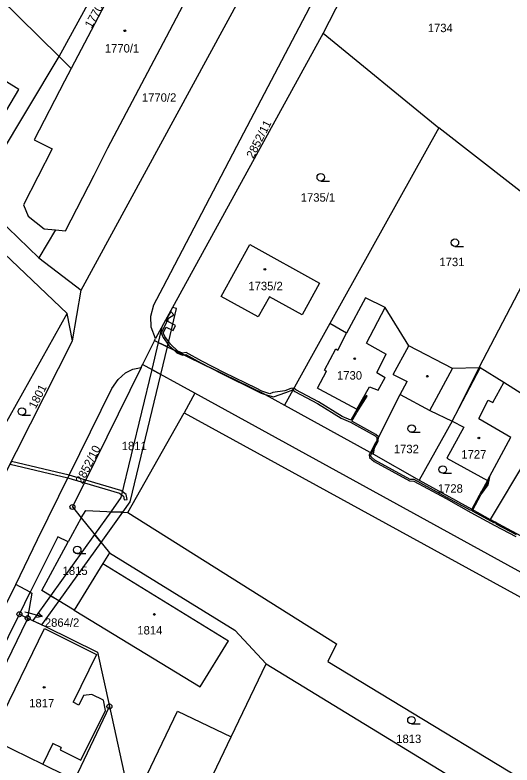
# Model space of a CAD drawing. Extents: x -562167 to -556918, y -1077891 to -1070763.
# Drawn here: x -560310.5 to -560210.1, y -1076020.6 to -1075869.3 of the extents above; entities that cross this region are included whole.
import ezdxf

# ---------------------------------------------------------------- set-up
doc = ezdxf.new("R2010")
doc.units = 0
for name, color, linetype in [('Hranice parcel', 7, 'Continuous'), ('Parcelní čísla', 7, 'Continuous'), ('Pop  PČ popisy', 7, 'Continuous'), ('Vnitřní kresba', 7, 'Continuous'), ('Věcná břemena k části', 7, 'Continuous'), ('Značky bodu BP', 7, 'Continuous'), ('Značky budov', 7, 'Continuous'), ('Značky kultur', 7, 'Continuous')]:
    doc.layers.add(name, color=color, linetype=linetype)

msp = doc.modelspace()

# ---------------------------------------------------------------- linework, layer by layer
at = {"layer": 'Hranice parcel'}
for p, q in [((-560230.82, -1075838.69), (-560248.25, -1075872.91)), ((-560301.63, -1075877.64), (-560284.07, -1075845.5)), ((-560314.48, -1075865.02), (-560301.63, -1075877.64)), ((-560297.13, -1075924.79), (-560264.77, -1075865.28)), ((-560248.25, -1075872.91), (-560224.91, -1075892)), ((-560318.55, -1075905.86), (-560301.63, -1075877.64)), ((-560299.2, -1075880.03), (-560301.63, -1075877.64)), ((-560224.91, -1075892), (-560246.92, -1075931.49)), ((-560299.96, -1075929.47), (-560327.78, -1075903.07)), ((-560318.55, -1075905.86), (-560305.73, -1075918.26)), ((-560201.24, -1075910.47), (-560216.83, -1075940.47)), ((-560302.31, -1075912.61), (-560305.73, -1075918.26)), ((-560305.73, -1075918.26), (-560297.13, -1075924.79)), ((-560298.93, -1075934.98), (-560297.13, -1075924.79)), ((-560316.85, -1075959.58), (-560299.96, -1075929.47)), ((-560298.93, -1075934.98), (-560299.96, -1075929.47)), ((-560246.92, -1075931.49), (-560256.11, -1075947.97)), ((-560313.03, -1075962.89), (-560298.93, -1075934.98)), ((-560282.36, -1075934.94), (-560284.75, -1075939.78)), ((-560282.36, -1075934.94), (-560282.12, -1075934.51)), ((-560285.06, -1075940.41), (-560284.75, -1075939.78)), ((-560274.17, -1075945.59), (-560284.75, -1075939.78)), ((-560216.83, -1075940.47), (-560222.26, -1075951.21)), ((-560274.17, -1075945.59), (-560276.38, -1075949.51)), ((-560256.11, -1075947.97), (-560238.13, -1075957.86)), ((-560287.75, -1075969.63), (-560276.38, -1075949.51)), ((-560222.26, -1075951.21), (-560228.92, -1075963.09)), ((-560238.13, -1075957.86), (-560228.92, -1075963.09)), ((-560228.92, -1075963.09), (-560218.25, -1075969)), ((-560218.25, -1075969), (-560214.59, -1075971.02)), ((-560297.16, -1075970.69), (-560299.8, -1075975.58)), ((-560297.16, -1075970.69), (-560291.45, -1075977.77)), ((-560203.7, -1075976.91), (-560214.59, -1075971.02)), ((-560307.42, -1075985.72), (-560310.34, -1075984.19)), ((-560309.62, -1075990.16), (-560307.42, -1075985.72)), ((-560320.84, -1076012.83), (-560309.62, -1075990.16)), ((-560309.62, -1075990.16), (-560307.96, -1075990.95)), ((-560293.84, -1075997.85), (-560291.45, -1076008.78)), ((-560298.46, -1076023.54), (-560291.45, -1076008.78)), ((-560291.45, -1076008.78), (-560287.01, -1076029.07))]:
    msp.add_line(p, q, dxfattribs=at)
for points in [[(-560282.12, -1075934.51), (-560283, -1075932.25), (-560283.08, -1075930.01), (-560282.46, -1075927.75), (-560280.62, -1075924.18), (-560265.72, -1075895.71), (-560246.83, -1075859.69), (-560227.16, -1075822.08), (-560208.85, -1075787.15), (-560196.56, -1075763.61), (-560182.19, -1075736.22), (-560178.49, -1075729.15), (-560177.53, -1075727.83), (-560176.47, -1075727.17), (-560174.73, -1075726.87), (-560173.46, -1075727.12), (-560172.47, -1075727.43)], [(-560259.43, -1075855.45), (-560278.52, -1075840.5), (-560284.42, -1075847.79), (-560282.72, -1075848.76), (-560289.71, -1075861.98), (-560299.2, -1075880.03)], [(-560302.31, -1075912.61), (-560300.29, -1075912.81), (-560294.55, -1075901.59), (-560291.76, -1075896.06), (-560279.95, -1075873.64), (-560273.19, -1075860.8), (-560264.77, -1075865.28)], [(-560248.25, -1075872.91), (-560281.71, -1075933.76), (-560282.12, -1075934.51)], [(-560314.87, -1075892.81), (-560309.71, -1075884.28), (-560318.18, -1075879.13), (-560323.33, -1075887.57), (-560314.87, -1075892.81)], [(-560299.2, -1075880.03), (-560300.53, -1075882.57), (-560306.65, -1075894.41), (-560303.01, -1075896.29), (-560308.77, -1075907.55), (-560307.89, -1075909.86), (-560304.62, -1075912.37), (-560302.31, -1075912.61)], [(-560201.24, -1075910.47), (-560202.7, -1075909.33), (-560224.91, -1075892)], [(-560263.11, -1075915.53), (-560249, -1075923.36), (-560252.54, -1075929.73), (-560259.12, -1075926.12), (-560261.38, -1075930.14), (-560268.88, -1075926.04), (-560263.11, -1075915.53)], [(-560216.83, -1075940.47), (-560222.13, -1075940.56), (-560230.97, -1075936.01), (-560235.79, -1075928.3), (-560239.71, -1075926.3), (-560243.54, -1075933.47), (-560246.92, -1075931.49)], [(-560282.36, -1075934.94), (-560280.6, -1075935.79), (-560260, -1075945.81), (-560256.11, -1075947.97)], [(-560310.34, -1075984.19), (-560305.94, -1075975.06), (-560290.93, -1075944.64), (-560289.66, -1075942.77), (-560288.18, -1075941.45), (-560286.72, -1075940.71), (-560285.06, -1075940.41)], [(-560285.06, -1075940.41), (-560298.91, -1075968.52), (-560297.16, -1075970.69)], [(-560201.73, -1075949.81), (-560211.79, -1075943.38), (-560216.58, -1075940.47), (-560216.83, -1075940.47)], [(-560101.22, -1076047.06), (-560101.56, -1076040.32), (-560106.23, -1076037.76), (-560274.17, -1075945.59)], [(-560238.13, -1075957.86), (-560237.81, -1075955.82), (-560232.72, -1075945.82), (-560226.74, -1075949.05), (-560222.26, -1075951.21)], [(-560276.38, -1075949.51), (-560175.37, -1076004.82), (-560101.22, -1076047.06)], [(-560201.73, -1075949.81), (-560204.4, -1075954.04), (-560207.21, -1075958.83), (-560214.59, -1075971.02)], [(-560222.26, -1075951.21), (-560219.89, -1075952.41), (-560223.34, -1075958.67), (-560215.12, -1075963.19), (-560218.25, -1075969)], [(-560297.16, -1075970.69), (-560296.19, -1075969.25), (-560287.75, -1075969.63)], [(-560287.75, -1075969.63), (-560245.59, -1075996.12), (-560247.34, -1075999.72), (-560193.82, -1076032.1), (-560209.15, -1076062.88)], [(-560299.8, -1075975.58), (-560301.89, -1075974.55), (-560307.42, -1075985.72)], [(-560291.45, -1075977.77), (-560292.75, -1075979.9), (-560298.54, -1075989.32), (-560305.1, -1075985.41), (-560299.8, -1075975.58)], [(-560291.45, -1075977.77), (-560266.12, -1075993.37), (-560259.81, -1076000.19)], [(-560329.29, -1076028.06), (-560329.52, -1076027.63), (-560329.7, -1076027.17), (-560329.99, -1076025.7), (-560330.08, -1076025.18), (-560330.12, -1076024.66), (-560329.9, -1076023.7), (-560329.53, -1076022.45), (-560310.34, -1075984.19)], [(-560307.42, -1075985.72), (-560307.09, -1075985.89), (-560307.96, -1075990.95)], [(-560307.96, -1075990.95), (-560308.05, -1075991.55), (-560308.19, -1075991.48), (-560319.06, -1076013.73)], [(-560307.96, -1075990.95), (-560304.34, -1075992.67), (-560293.84, -1075997.85)], [(-560271.9, -1076025.48), (-560266.86, -1076014.94), (-560259.81, -1076000.19)], [(-560259.81, -1076000.19), (-560206.32, -1076032.77), (-560218.6, -1076057.26)]]:
    msp.add_lwpolyline(points, dxfattribs=at)
at = {"layer": 'Pop  PČ popisy'}
for p, q in [((-560308.5, -1075989.69), (-560307.95, -1075989.84)), ((-560307.95, -1075989.84), (-560305.05, -1075990.62)), ((-560305.05, -1075990.62), (-560305.89, -1075989.87)), ((-560305.05, -1075990.62), (-560306.15, -1075990.84))]:
    msp.add_line(p, q, dxfattribs=at)
at = {"layer": 'Vnitřní kresba'}
for p, q in [((-560239.56, -1075935.49), (-560235.79, -1075928.3)), ((-560245.35, -1075936.85), (-560243.54, -1075933.47)), ((-560239.56, -1075935.49), (-560235.53, -1075937.67)), ((-560248, -1075940.92), (-560245.75, -1075936.59)), ((-560245.75, -1075936.59), (-560245.35, -1075936.85)), ((-560234.14, -1075941.79), (-560230.97, -1075936.01)), ((-560237.42, -1075941.39), (-560235.53, -1075937.67)), ((-560249.45, -1075944.52), (-560247.62, -1075941.09)), ((-560248, -1075940.92), (-560247.62, -1075941.09)), ((-560237.42, -1075941.39), (-560235.75, -1075942.41)), ((-560226.74, -1075949.05), (-560222.13, -1075940.56)), ((-560222.26, -1075951.21), (-560216.58, -1075940.47)), ((-560237.18, -1075944.93), (-560235.75, -1075942.41)), ((-560234.14, -1075941.79), (-560231.34, -1075943.22)), ((-560249.45, -1075944.52), (-560249.02, -1075944.75)), ((-560241.48, -1075948.78), (-560238.93, -1075944.31)), ((-560238.93, -1075944.31), (-560237.18, -1075944.93)), ((-560232.72, -1075945.82), (-560231.34, -1075943.22)), ((-560214.02, -1075947.47), (-560211.79, -1075943.38)), ((-560249.02, -1075944.75), (-560241.48, -1075948.78)), ((-560216.87, -1075950.68), (-560214.95, -1075946.97)), ((-560214.95, -1075946.97), (-560214.02, -1075947.47)), ((-560216.87, -1075950.68), (-560210.36, -1075954.42)), ((-560215.12, -1075963.19), (-560210.36, -1075954.42)), ((-560292.75, -1075979.9), (-560267.42, -1075995.51)), ((-560298.54, -1075989.32), (-560273.1, -1076004.84)), ((-560315.44, -1076015.32), (-560304.54, -1075993.08)), ((-560304.54, -1075993.08), (-560294.06, -1075998.3)), ((-560273.1, -1076004.84), (-560267.42, -1075995.51)), ((-560294.06, -1075998.3), (-560298.76, -1076007.92)), ((-560296.67, -1076006.57), (-560297.63, -1076008.49)), ((-560294.97, -1076006.35), (-560296.67, -1076006.57)), ((-560292.64, -1076007.52), (-560294.97, -1076006.35)), ((-560297.63, -1076008.49), (-560298.76, -1076007.92)), ((-560292.22, -1076009.6), (-560292.64, -1076007.52)), ((-560297.21, -1076019.59), (-560292.22, -1076009.6)), ((-560287.01, -1076029.07), (-560277.71, -1076009.7)), ((-560277.71, -1076009.7), (-560266.86, -1076014.94)), ((-560315.44, -1076015.32), (-560304.89, -1076020.44)), ((-560302.85, -1076016.28), (-560304.89, -1076020.44)), ((-560301.2, -1076017.07), (-560302.85, -1076016.28)), ((-560301.2, -1076017.07), (-560301.42, -1076017.52)), ((-560301.42, -1076017.52), (-560297.21, -1076019.59)), ((-560304.89, -1076020.44), (-560300.38, -1076022.61))]:
    msp.add_line(p, q, dxfattribs=at)
at = {"layer": 'Věcná břemena k části'}
for points in [[(-560277.89, -1075928.5), (-560278.71, -1075928.3), (-560280.83, -1075932.16), (-560281.59, -1075935.31), (-560279.74, -1075936.21)], [(-560279.13, -1075935.67), (-560280.27, -1075934.11), (-560280.59, -1075933.39), (-560279.97, -1075932.21), (-560278.6, -1075932.91), (-560278.08, -1075931.89), (-560279.68, -1075931.08), (-560279.52, -1075930.43), (-560278.44, -1075929.77), (-560279.04, -1075929.05), (-560279.8, -1075930.29), (-560280.01, -1075931.43), (-560281.03, -1075933.37), (-560280.61, -1075934.31), (-560279.43, -1075935.93), (-560278.47, -1075936.83), (-560276.35, -1075937.85), (-560276, -1075937.79), (-560272.99, -1075939.44), (-560271.2, -1075940.36), (-560260, -1075945.81), (-560258.28, -1075946.32), (-560255.81, -1075945.45), (-560254.41, -1075944.92), (-560254.21, -1075944.56), (-560254.84, -1075944.6), (-560256.01, -1075945.09), (-560258.45, -1075945.43), (-560259.02, -1075945.68), (-560260.65, -1075945.18), (-560261.81, -1075944.57), (-560268.21, -1075941.45), (-560272.81, -1075939.08), (-560275.94, -1075937.37), (-560276.67, -1075937.5), (-560277.6, -1075937.09)], [(-560279.74, -1075936.21), (-560281.59, -1075935.31), (-560282.91, -1075940.79), (-560281.08, -1075941.79)], [(-560278.47, -1075936.83), (-560277.82, -1075937.43), (-560276.71, -1075937.92), (-560276.35, -1075937.85)], [(-560281.08, -1075941.79), (-560282.91, -1075940.79), (-560289.11, -1075966.63), (-560291.15, -1075969.48), (-560288.77, -1075969.58), (-560287.25, -1075967.47)], [(-560271.2, -1075940.36), (-560268.39, -1075941.81), (-560261.99, -1075944.93), (-560260.81, -1075945.56), (-560260, -1075945.81)], [(-560237.95, -1075956.7), (-560237.16, -1075955.24), (-560237.12, -1075954.47), (-560237.12, -1075954.38), (-560237.62, -1075953.9), (-560242.47, -1075951.18), (-560241.49, -1075949.46), (-560239.37, -1075946.17), (-560239.62, -1075946.01), (-560241.75, -1075949.3), (-560242.71, -1075951), (-560244.47, -1075950.25), (-560249.21, -1075947.32), (-560253.79, -1075944.87), (-560254.21, -1075944.56), (-560254.41, -1075944.92), (-560254.01, -1075945.21), (-560249.43, -1075947.66), (-560244.65, -1075950.61), (-560242.76, -1075951.42), (-560237.8, -1075954.14), (-560237.42, -1075954.5), (-560237.46, -1075955.13), (-560237.46, -1075955.16), (-560237.69, -1075955.58), (-560238.74, -1075957.52), (-560238.47, -1075957.67)], [(-560311.23, -1075959.34), (-560311.51, -1075959.89), (-560299.82, -1075962.66), (-560299.55, -1075962.11)], [(-560299.82, -1075962.66), (-560299.66, -1075962.7), (-560296.51, -1075963.64), (-560289.44, -1075965.75), (-560288.6, -1075966.36), (-560288.48, -1075967.1), (-560287.88, -1075967), (-560288.06, -1075966.02), (-560289.16, -1075965.21), (-560296.24, -1075963.1), (-560299.55, -1075962.11)], [(-560214.98, -1075964.05), (-560214.56, -1075962.15), (-560215.12, -1075963.19), (-560215.26, -1075963.93), (-560216.28, -1075965.35), (-560218.25, -1075969), (-560218.03, -1075969.12), (-560216.45, -1075966.1)], [(-560288.77, -1075969.58), (-560291.15, -1075969.48), (-560294.44, -1075974.06), (-560293.14, -1075975.67)], [(-560293.14, -1075975.67), (-560294.44, -1075974.06), (-560303.34, -1075986.46), (-560301.62, -1075987.48)], [(-560301.62, -1075987.48), (-560303.34, -1075986.46), (-560306.92, -1075991.44), (-560305.09, -1075992.32)]]:
    msp.add_lwpolyline(points, close=True, dxfattribs=at)
msp.add_lwpolyline([(-560209.22, -1075974.13), (-560213.35, -1075972), (-560213.24, -1075971.8), (-560213.57, -1075971.62), (-560213.68, -1075971.81), (-560218.15, -1075969.34), (-560218.03, -1075969.12), (-560218.25, -1075969), (-560218.29, -1075968.98), (-560218.43, -1075969.24), (-560223.29, -1075966.58), (-560229.9, -1075963.01), (-560230.74, -1075962.95), (-560237.83, -1075959.08), (-560238.62, -1075958.4), (-560238.68, -1075958.05), (-560238.47, -1075957.67), (-560238.74, -1075957.52), (-560239, -1075958), (-560238.9, -1075958.56), (-560238.01, -1075959.32), (-560230.82, -1075963.25), (-560229.98, -1075963.31), (-560223.43, -1075966.84), (-560218.47, -1075969.62), (-560213.64, -1075972.29), (-560209.4, -1075974.49)], dxfattribs=at)
at = {"layer": 'Značky bodu BP'}
for centre, radius in [((-560298.91, -1075968.52), 0.5), ((-560298.91, -1075968.52), 0.0303), ((-560309.62, -1075990.16), 0.5), ((-560309.62, -1075990.16), 0.0303), ((-560307.96, -1075990.95), 0.5), ((-560307.96, -1075990.95), 0.0303), ((-560291.45, -1076008.78), 0.5), ((-560291.45, -1076008.78), 0.0303)]:
    msp.add_circle(centre, radius, dxfattribs=at)
at = {"layer": 'Značky budov'}
for centre in [(-560288.34, -1075872.43), (-560260.05, -1075920.58), (-560241.92, -1075938.6), (-560227.25, -1075942.14), (-560216.83, -1075954.6), (-560282.37, -1075990.21), (-560304.62, -1076004.91)]:
    msp.add_circle(centre, 0.175, dxfattribs=at)
at = {"layer": 'Značky kultur'}
for p, q in [((-560248.77, -1075902.75), (-560247.02, -1075902.75)), ((-560221.67, -1075915.94), (-560219.92, -1075915.94)), ((-560309.12, -1075950.01), (-560307.37, -1075950.01)), ((-560230.41, -1075953.46), (-560228.66, -1075953.46)), ((-560224.14, -1075961.72), (-560222.39, -1075961.72)), ((-560297.94, -1075977.94), (-560296.19, -1075977.94)), ((-560230.46, -1076012.29), (-560228.71, -1076012.29))]:
    msp.add_line(p, q, dxfattribs=at)
for centre in [(-560248.77, -1075902), (-560221.67, -1075915.19), (-560309.12, -1075949.26), (-560230.41, -1075952.71), (-560224.14, -1075960.97), (-560297.94, -1075977.19), (-560230.46, -1076011.54)]:
    msp.add_circle(centre, 0.75, dxfattribs=at)

# ---------------------------------------------------------------- texts
at = {"layer": 'Parcelní čísla'}
for s, rotation, p in [('1770/3', 61, (-560295.07, -1075872.06)), ('2852/11', 63, (-560262.39, -1075898.34)), ('1801', 63, (-560306.35, -1075948.86)), ('2852/10', 63, (-560296.9, -1075963.98))]:
    msp.add_text(s, height=1.7, rotation=rotation, dxfattribs=at).set_placement(p)
for s, p in [('1734', (-560227.16, -1075872.71)), ('1770/1', (-560292.38, -1075876.83)), ('1770/2', (-560284.89, -1075886.75)), ('1735/1', (-560252.81, -1075906.92)), ('1731', (-560224.81, -1075919.93)), ('1735/2', (-560263.39, -1075924.79)), ('1730', (-560245.49, -1075942.82)), ('1811', (-560288.96, -1075957.06)), ('1732', (-560234.01, -1075957.67)), ('1727', (-560220.38, -1075958.75)), ('1728', (-560225.13, -1075965.64)), ('1815', (-560300.9, -1075982.24)), ('2864/2', (-560304.49, -1075992.7)), ('1814', (-560285.81, -1075994.25)), ('1817', (-560307.65, -1076008.96)), ('1813', (-560233.53, -1076016.16))]:
    msp.add_text(s, height=1.7, dxfattribs=at).set_placement(p)

doc.saveas('drawing.dxf')
